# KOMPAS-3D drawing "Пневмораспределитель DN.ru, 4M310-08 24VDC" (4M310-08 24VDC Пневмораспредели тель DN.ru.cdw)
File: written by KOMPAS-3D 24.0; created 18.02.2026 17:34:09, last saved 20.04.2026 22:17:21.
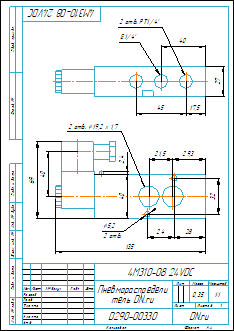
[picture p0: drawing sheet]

Document properties: Автор: R2D2; Форматы листов документа: A4; Полное имя файла: 4M310-08 24VDC Пневмораспределитель DN.ru.m3d; Масса: 0.35; Наименование: Пневмораспределитель DN.ru; Количество листов документа: 1; Примечание: D290-00330

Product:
- Part/product: Пневмораспределитель DN.ru  | designation 4M310-08 24VDC
    Масса: 0.35
    Раздел спецификации: Прочие изделия
    Примечание: D290-00330

Views: Вид 1, Спереди, Проекционный вид 2
Referenced files in E:\Работа\Зайцев\Аксессуары для пневмоприводов\Пневмораспределители DN.ru\4М310-08 NAMUR Пневмораспределитель DN.RU\4М310-08 24VDC NAMUR Пневмораспределитель DN.RU\: 4M310-08 24VDC Пневмораспределитель DN.ru.m3d
Referenced files in E:\Работа\Зайцев\Для компаса\: чертеж DN.ru.cdt
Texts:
  чертеж DN.ru.cdt
  Пневмораспредели
  тель DN.ru
  Пневмораспределитель DN.ru
  4M310-08 24VDC Пневмораспределитель DN.ru
Dimensions and other numbers on the sheet: 0; 3; 2; 4; 2 отв. PT1/4'; 27; 40; 17,5; 45; 4M310-08 24VDC; 69; 24; 28; 32; 29,3; 21,5; 135; 2,4; 5,2; 2 отв.; 2 отв.  19,2 х 1,7; 1:1; 1; 0,35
